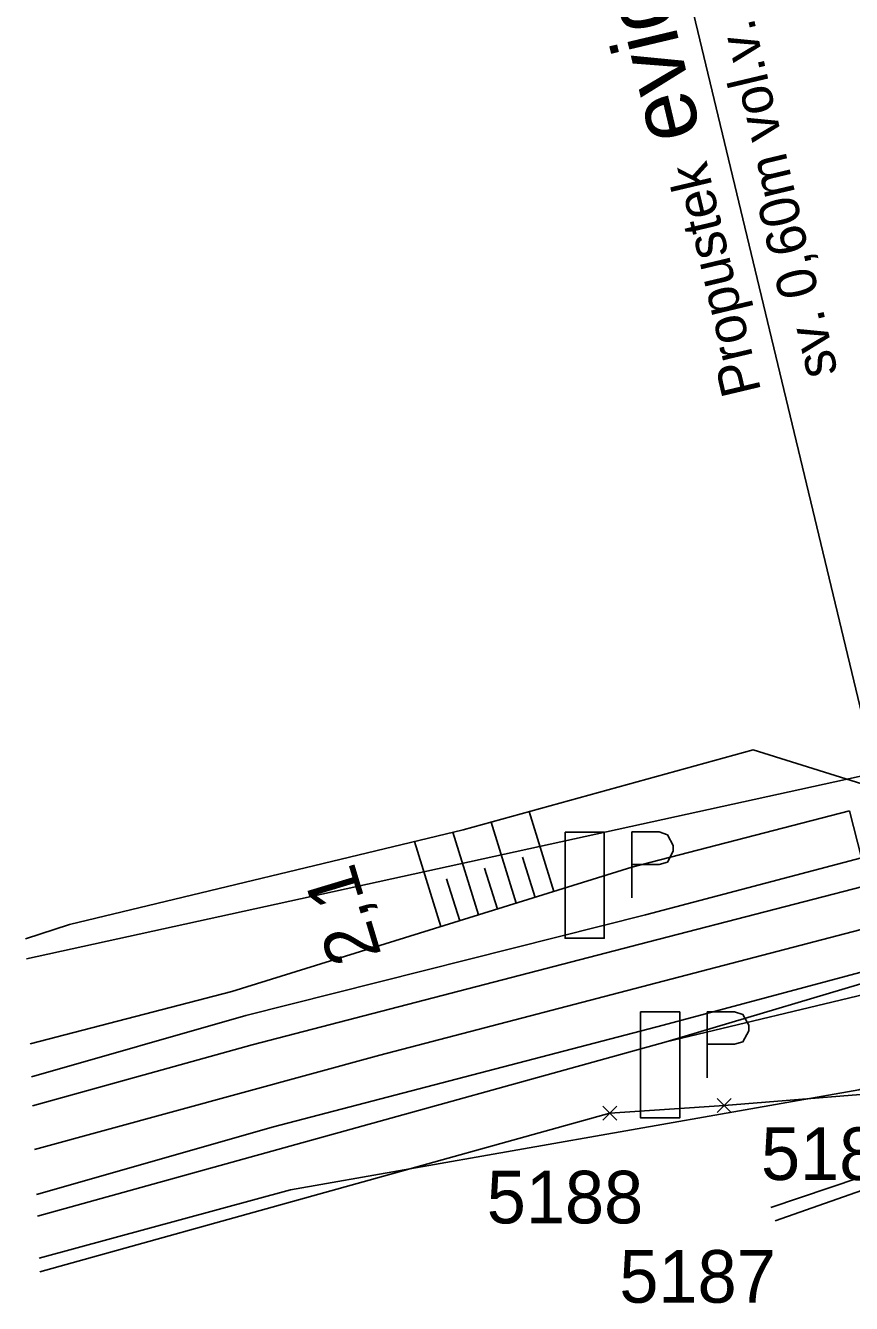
# Model space of a CAD drawing. Extents: x -806456 to -805395, y -1150847 to -1150506.
# Drawn here: x -806238.96 to -806207.56, y -1150731.92 to -1150683.33 of the extents above; entities that cross this region are included whole.
import ezdxf

# ---------------------------------------------------------------- set-up
doc = ezdxf.new("R2010")
doc.units = 0
for name, color, linetype in [('0381KM032-037P - Vrstva 1', 7, 'Continuous'), ('0381KM032-037P - Vrstva 17', 7, 'Continuous'), ('0381KM032-037P - Vrstva 19', 7, 'Continuous'), ('0381KM032-037P - Vrstva 36', 7, 'Continuous'), ('0381KM032-037P - Vrstva 4', 7, 'Continuous'), ('0381KM032-037P - Vrstva 48', 7, 'Continuous'), ('0381KM032-037P - Vrstva 49', 7, 'Continuous'), ('0381KM032-037P - Vrstva 51', 7, 'Continuous'), ('szdc - hran DP', 7, 'Continuous'), ('szdc - szdc_cislo', 7, 'Continuous'), ('szdc - szdc_krizek', 7, 'Continuous')]:
    doc.layers.add(name, color=color, linetype=linetype)

msp = doc.modelspace()

# ---------------------------------------------------------------- linework, layer by layer
at = {"layer": '0381KM032-037P - Vrstva 1'}
for points in [[(-805989.76, -1150661.17), (-806027.03, -1150670.9), (-806064.32, -1150680.56), (-806101.67, -1150690.24), (-806138.44, -1150699.75), (-806158.28, -1150704.94), (-806163.64, -1150706.34), (-806175.38, -1150709.4), (-806186.46, -1150712.29), (-806205.201, -1150717.188), (-806213.26, -1150719.29)], [(-806213.26, -1150719.29), (-806225.487, -1150722.48), (-806238.622, -1150726.073)]]:
    msp.add_lwpolyline(points, dxfattribs=at)
at = {"layer": '0381KM032-037P - Vrstva 17'}
msp.add_lwpolyline([(-806210.617, -1150728.275), (-806197.196, -1150723.748), (-806191.898, -1150721.811)], dxfattribs=at)
at = {"layer": '0381KM032-037P - Vrstva 19'}
msp.add_line((-806205.929, -1150714.672), (-806217.278, -1150667.349), dxfattribs=at)
at = {"layer": '0381KM032-037P - Vrstva 36'}
for points in [[(-806218.444, -1150714.003), (-806216.955, -1150714.003), (-806216.955, -1150718.032), (-806218.444, -1150718.032)], [(-806215.575, -1150720.837), (-806214.086, -1150720.837), (-806214.086, -1150724.866), (-806215.575, -1150724.866)]]:
    msp.add_lwpolyline(points, close=True, dxfattribs=at)
for points in [[(-806215.911, -1150716.502), (-806215.911, -1150713.994)], [(-806215.911, -1150713.994), (-806214.868, -1150713.994)], [(-806214.868, -1150713.994), (-806214.552, -1150714.099), (-806214.331, -1150714.505), (-806214.331, -1150714.726), (-806214.552, -1150715.142), (-806214.868, -1150715.232)], [(-806214.868, -1150715.232), (-806215.911, -1150715.232)], [(-806213.042, -1150723.336), (-806213.042, -1150720.828)], [(-806213.042, -1150720.828), (-806211.999, -1150720.828)], [(-806211.999, -1150720.828), (-806211.683, -1150720.933), (-806211.462, -1150721.339), (-806211.462, -1150721.56), (-806211.683, -1150721.976), (-806211.999, -1150722.066)], [(-806211.999, -1150722.066), (-806213.042, -1150722.066)]]:
    msp.add_lwpolyline(points, dxfattribs=at)
at = {"layer": '0381KM032-037P - Vrstva 4'}
for points in [[(-806173.358, -1150707), (-806179.992, -1150708.144), (-806186.437, -1150710.716), (-806215.256, -1150718.168), (-806230.349, -1150722.089), (-806238.693, -1150724.411)], [(-806176.794, -1150711.837), (-806190.006, -1150714.82), (-806200.085, -1150717.418), (-806214.718, -1150721.345), (-806229.528, -1150725.211), (-806238.55, -1150727.775)], [(-806207.177, -1150714.974), (-806215.394, -1150717.144), (-806230.58, -1150720.973), (-806238.74, -1150723.305)], [(-806205.415, -1150719.241), (-806214.6, -1150721.97), (-806229.14, -1150726.003), (-806238.515, -1150728.599)]]:
    msp.add_lwpolyline(points, dxfattribs=at)
at = {"layer": '0381KM032-037P - Vrstva 48'}
for p, q in [((-806218.872, -1150716.258), (-806219.816, -1150713.219)), ((-806221.737, -1150717.148), (-806222.714, -1150714.003)), ((-806220.305, -1150716.703), (-806221.263, -1150713.617)), ((-806223.17, -1150717.593), (-806224.176, -1150714.355)), ((-806219.589, -1150716.48), (-806220.064, -1150714.949)), ((-806221.021, -1150716.925), (-806221.504, -1150715.371)), ((-806222.453, -1150717.37), (-806222.949, -1150715.775))]:
    msp.add_line(p, q, dxfattribs=at)
at = {"layer": '0381KM032-037P - Vrstva 49'}
for p, q in [((-806207.177, -1150714.974), (-806207.636, -1150713.191)), ((-806214.6, -1150721.97), (-806205.259, -1150719.74))]:
    msp.add_line(p, q, dxfattribs=at)
for points in [[(-806206.314, -1150712.425), (-806211.288, -1150710.871), (-806222.32, -1150713.908), (-806237.293, -1150717.516), (-806238.963, -1150718.052)], [(-806176.794, -1150711.837), (-806184.135, -1150716.013), (-806184.517, -1150716.193), (-806189.244, -1150717.541), (-806198.367, -1150720.903), (-806207.279, -1150723.797), (-806228.886, -1150727.595), (-806238.447, -1150730.204)], [(-806207.636, -1150713.191), (-806215.906, -1150715.336), (-806231.117, -1150720.062), (-806238.793, -1150722.055)], [(-806214.6, -1150721.97), (-806229.14, -1150726.003), (-806238.515, -1150728.599)]]:
    msp.add_lwpolyline(points, dxfattribs=at)
at = {"layer": '0381KM032-037P - Vrstva 51'}
msp.add_line((-806195.218, -1150723.443), (-806210.458, -1150728.774), dxfattribs=at)
at = {"layer": 'szdc - hran DP'}
for p, q in [((-806238.93, -1150718.822), (-806172.99, -1150704.37)), ((-806207.21, -1150723.98), (-806212.4, -1150724.39)), ((-806216.74, -1150724.69), (-806238.425, -1150730.722)), ((-806212.4, -1150724.39), (-806216.74, -1150724.69))]:
    msp.add_line(p, q, dxfattribs=at)
at = {"layer": 'szdc - szdc_krizek'}
for p, q in [((-806212.135, -1150724.655), (-806212.666, -1150724.125)), ((-806212.666, -1150724.655), (-806212.135, -1150724.125)), ((-806216.475, -1150724.955), (-806217.006, -1150724.425)), ((-806217.006, -1150724.955), (-806216.475, -1150724.425))]:
    msp.add_line(p, q, dxfattribs=at)

# ---------------------------------------------------------------- texts
at = {"layer": '0381KM032-037P - Vrstva 19'}
for s, height, p in [('evid. km 35,412', 2.5, (-806213.267, -1150687.448)), ('sv. 0,60m vol.v. 0,80m', 1.5, (-806208.064, -1150696.537)), ('Propustek', 1.5, (-806210.982, -1150697.231))]:
    msp.add_text(s, height=height, rotation=103.3643, dxfattribs=at).set_placement(p)
at = {"layer": '0381KM032-037P - Vrstva 48'}
msp.add_text('2,1', height=2, rotation=106.7815, dxfattribs=at).set_placement((-806225.421, -1150718.663))
at = {"layer": 'szdc - szdc_cislo'}
for s, p in [('5186', (-806210.996, -1150727.227)), ('5188', (-806221.426, -1150728.877)), ('5187', (-806216.383, -1150731.893))]:
    msp.add_text(s, height=2, dxfattribs=at).set_placement(p)

doc.saveas('drawing.dxf')
